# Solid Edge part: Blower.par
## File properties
Author: CADCIM
Template: NORMENG.PAR
Last saved by: TIET
Revision: 11
Application: Solid Edge
Accuracy: 0.99
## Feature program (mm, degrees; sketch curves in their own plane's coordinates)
sketch for "unnamed RevolvedProtrusion 1" #1 plane through (0, 0, 0) normal (0, -1, 0) x-axis (1, 0, 0)
  line (0, 171.45) -> (139.7, 171.45)
  line (139.7, 171.45) -> (139.7, 165.1)
  line (139.7, 165.1) -> (0, 165.1)
  line (0, 165.1) -> (0, 171.45)
sketch for "unnamed RevolvedProtrusion 1" #2 plane through (0, 0, 0) normal (0, -1, 0) x-axis (1, 0, 0)
  line (0, 0) -> (0, 0)
  line (0, 0) -> (0, 0)
  line (139.7, 0) -> (139.7, -12.7)
  line (139.7, -12.7) -> (38.1, -12.7)
  line (38.1, -12.7) -> (38.1, -76.2)
  line (38.1, -76.2) -> (0, -76.2)
  line (0, -76.2) -> (0, 0)
  line (0, 0) -> (139.7, 0)
  dimension (linear) = 38.1
  dimension (linear) = 139.7
revolve "unnamed RevolvedProtrusion 1" add finite 360 deg
sketch for "unnamed Protrusion 1" plane through (0, 0, 0) normal (0, 0, 1) x-axis (1, 0, 0)
  line (76.708, 0) -> (139.7, 0)
  line (127.6948, -46.4771) -> (131.2751, -47.7802)
  line (76.708, -6.35) -> (135.0219, -6.35)
  line (76.708, 0) -> (76.708, -6.35)
  dimension (linear) = 127.6948
  dimension (linear) = 76.708
extrude "unnamed Protrusion 1" add through along +normal
pattern "unnamed Pattern 1" of "unnamed Protrusion 1"
extrude "unnamed Protrusion 2" add through
extrude "unnamed Protrusion 3" add through
extrude "unnamed Protrusion 4" add through
extrude "unnamed Protrusion 5" add through
extrude "unnamed Protrusion 6" add through
sketch for "unnamed Hole 1" plane through (0, 0, -76.2) normal (0, 0, -1) x-axis (1, 0, 0)
hole "unnamed Hole 1" through
sketch for "ExtrudedCutout_1" plane through (0, 0, 171.45) normal (0, 0, 1) x-axis (0, -1, 0)
extrude "ExtrudedCutout_1" cut finite 6.35 along -normal
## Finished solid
Body 1: solid body, 50 faces, 139 edges, 84 vertices.
  Faces by surface: plane 40, cylinder 10
  Edges by curve: line 96, circle 43
Bounding box of the edges (mm): 279.400 x 279.400 x 247.650, from (-139.7, -139.7, -76.2) to (139.7, 139.7, 171.45).
Cylindrical faces by radius (mm): R19.05 x1, R38.1 x1, R101.6 x1, R131.6115 x6, R139.7 x1
Planar faces by outward normal: +x 1, +y 2, +z 8, -x 1, -y 2, -z 8, oblique 18
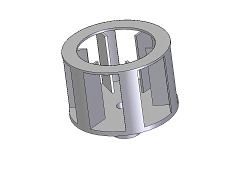
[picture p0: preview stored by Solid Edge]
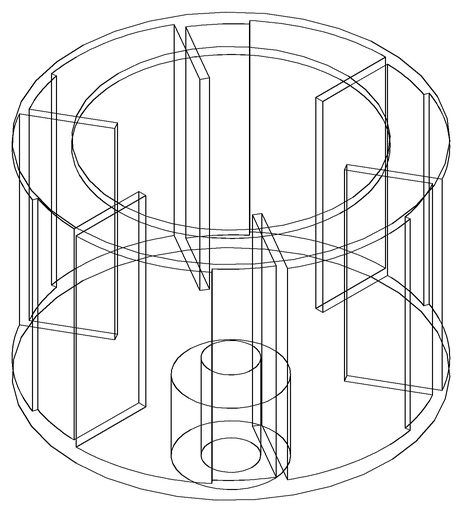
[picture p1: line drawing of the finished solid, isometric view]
